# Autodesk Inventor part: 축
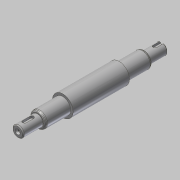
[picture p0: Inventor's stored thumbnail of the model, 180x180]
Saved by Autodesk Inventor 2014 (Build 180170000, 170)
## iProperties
Created: 2019-06
Part Number: 축
Material: 강철, 연강
Document SubType Name: Modeling
Designer: mduedu
Density: 1 g/cm^3
Appearance: 강철
Author: mduedu
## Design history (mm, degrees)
sketch "스케치1"
  geometry: L1 (0, 0)-(21, 0); L2 (21, 0)-(21, 6); L3 (21, 6)-(0, 6); L4 (0, 6)-(0, 0); L5 (21, 0)-(48, 0); L6 (48, 0)-(48, 8.5); L7 (48, 8.5)-(21, 8.5); L8 (21, 8.5)-(21, 0); L9 (48, 0)-(108, 0); L10 (108, 0)-(108, 11); L11 (108, 11)-(48, 11); L12 (48, 11)-(48, 0); L13 (108, 0)-(135, 0); L14 (135, 0)-(135, 8.5); L15 (135, 8.5)-(108, 8.5); L16 (108, 8.5)-(108, 0); L17 (135, 0)-(154, 0); L18 (154, 0)-(154, 6); L19 (154, 6)-(135, 6); L20 (135, 6)-(135, 0)
  constraints: 40 end point, 10 parallel, 5 horizontal, 5 perpendicular
  dimensions: "d3" = 60 distance of L10.end L11.end; "d4" = 17 diameter of L15 L13; "d5" = 22 diameter of L11 L9; "d6" = 17 diameter of L7 L5; "d7" = 12 diameter of L3 L1; "d40" = 19 distance of L18.end L19.end; "d41" = 12 diameter of L19 L17; "d42" = 46 distance between parallel lines of L10 L18; "d43" = 133 distance between parallel lines of L8 L18; "d44" = 154 distance between parallel lines of L4 L18
revolve "회전1" sketch "스케치1" stored, may be unused: angle "d9" = 90 deg
node "작업 평면1"
sketch "스케치2" dims "d10" = 12
  geometry: L1 (3.5, -2)-(-4.5, -2); L2 (-4.5, -2)-(-4.5, 2); L3 (-4.5, 2)-(3.5, 2); L4 (3.5, 2)-(3.5, -2); L5 (-10.5, 8.5)-(-10.5, -8.5) reference; 3 further points
  constraints: 8 end point, 2 midpoint, 2 parallel, 2 vertical alignment, 1 horizontal, 1 horizontal alignment, 1 perpendicular, 4 other
  dimensions: "d12" = 4 dimension on L5; "d13" = 4 distance between parallel lines of L3 L1
extrude "돌출1" cut sketch "스케치2" distance "d14" = 2.5; taper "d15" = 0 deg
sketch "스케치4"
  geometry: L1 (-143.5, 2)-(-135.5, 2); L2 (-135.5, 2)-(-135.5, -2); L3 (-135.5, -2)-(-143.5, -2); L4 (-143.5, -2)-(-143.5, 2); L5 (-143.5, 6)-(-143.5, -6) reference; 2 further points
  constraints: 8 end point, 2 parallel, 1 collinear, 1 horizontal, 1 horizontal alignment, 1 midpoint, 1 perpendicular, 1 vertical alignment, 2 other
  dimensions: "d50" = 10 dimension on L4; "d52" = 4 distance between parallel lines of L1 L3
extrude "돌출2" cut sketch "스케치4" distance "d53" = 2.5; taper "d54" = 0 deg
hole "구멍1" diameter "d18" = 3.242; stored, may be unused: countersink angle "d22" = 90 deg, drill point angle "d24" = 118 deg; dims "d16" = 10, "d17" = 10, "d19" = 8, "d20" = 4, "d21" = 2, "d23" = 10
sketch "스케치3"
  geometry: L1 (0, 0)-(2, 0); L2 (2, 0)-(2, -1.621); L3 (0, -2.776)-(0, 0); L4 (10, -1.621)-(0, -1.621) reference; L5 (0, -2.776)-(2, -1.621)
  constraints: 8 end point, 1 horizontal, 1 parallel, 1 perpendicular, 1 point on line
  dimensions: "d25" = 2 distance between parallel lines of L2 L3; "d27" = 30 deg angle of L1 L5
revolve "회전2" sketch "스케치3" stored, may be unused: angle "d29" = 90 deg
chamfer "모따기1" distance "d30" = 1.82; stored, may be unused: second distance "d31" = 2, angle "d32" = 30 deg
fillet "모깎기1" dims "d36" = 2, "d37" = 1
chamfer "모따기3" distance "d45" = 1.82; stored, may be unused: second distance "d46" = 2, angle "d47" = 30 deg
fillet "모깎기2" dims "d48" = 2, "d49" = 1
chamfer "모따기4" distance "d55" = 1; stored, may be unused: second distance "d56" = 2, angle "d57" = 30 deg
node "솔리드1"
